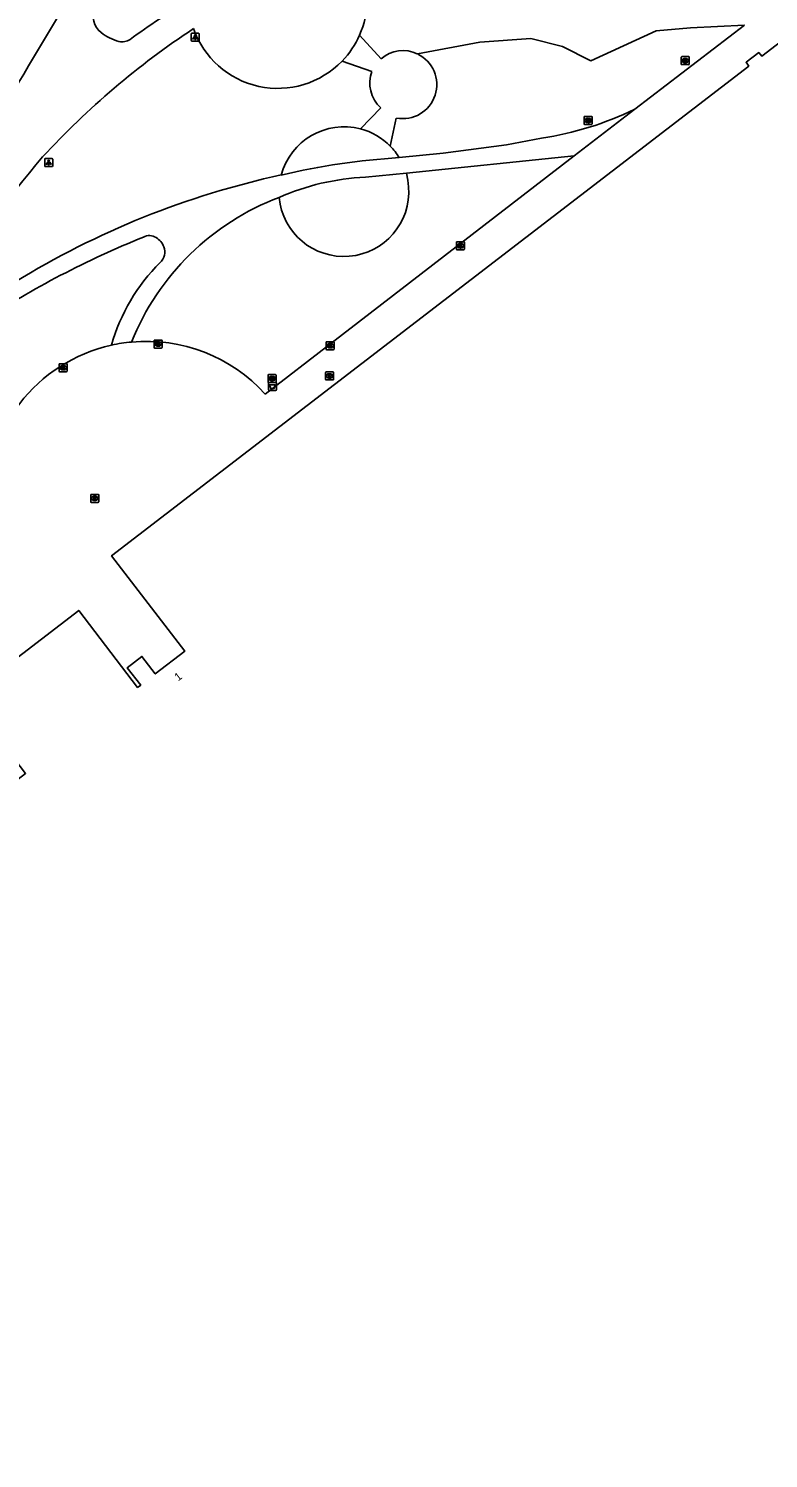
# Model space of a CAD drawing. Extents: x 155209 to 156823, y 385356 to 388482.
# Drawn here: x 156040.2 to 156132.6, y 385768.7 to 385947.3 of the extents above; entities that cross this region are included whole.
import ezdxf

# ---------------------------------------------------------------- set-up
doc = ezdxf.new("R2010")
doc.units = 0
for name, color, linetype in [('IMGEO_Afvalbak', 7, 'Continuous'), ('IMGEO_Brandkraan', 7, 'Continuous'), ('IMGEO_Groenvoorziening', 7, 'Continuous'), ('IMGEO_Kolk', 7, 'Continuous'), ('IMGEO_Lichtpunt', 7, 'Continuous'), ('IMGEO_Pand', 7, 'Continuous'), ('IMGEO_Pand_nummerreeks', 7, 'Continuous'), ('IMGEO_Rioolput', 7, 'Continuous'), ('IMGEO_Voetpad_gesloten', 7, 'Continuous'), ('IMGEO_Voetpad_open', 7, 'Continuous')]:
    doc.layers.add(name, color=color, linetype=linetype)

msp = doc.modelspace()

# ---------------------------------------------------------------- linework, layer by layer
at = {"layer": 'IMGEO_Afvalbak'}
for p, q in [((156070.18, 385902.2), (156070.18, 385903)), ((156070.18, 385903), (156070.18, 385902.2)), ((156070.28, 385903.1), (156071.07, 385903.1)), ((156071.07, 385903.1), (156070.28, 385903.1)), ((156071.07, 385902.1), (156070.28, 385902.1)), ((156070.28, 385902.1), (156071.07, 385902.1)), ((156071.17, 385903), (156071.17, 385902.2)), ((156071.17, 385902.2), (156071.17, 385903))]:
    msp.add_line(p, q, dxfattribs=at)
msp.add_lwpolyline([(156070.32, 385902.81), (156071.02, 385902.81), (156070.88, 385902.34), (156070.47, 385902.34), (156070.32, 385902.81)], dxfattribs=at)
for centre, start, end in [((156070.28, 385903), 90, 180), ((156070.28, 385903), 90, 180), ((156070.28, 385902.2), 180, 270), ((156070.28, 385902.2), 180, 270), ((156071.07, 385903), 0, 90), ((156071.07, 385903), 360, 90), ((156071.07, 385902.2), 270, 0), ((156071.07, 385902.2), 270, 0)]:
    msp.add_arc(centre, 0.1, start, end, dxfattribs=at)
at = {"layer": 'IMGEO_Brandkraan'}
for p, q in [((156077.31, 385903.49), (156077.31, 385904.34)), ((156077.39, 385904.42), (156078.24, 385904.42)), ((156078.24, 385903.41), (156077.39, 385903.41)), ((156077.8, 385904.19), (156077.83, 385904.19)), ((156077.82, 385903.64), (156077.8, 385903.64)), ((156078.31, 385904.34), (156078.31, 385903.49))]:
    msp.add_line(p, q, dxfattribs=at)
for points in [[(156077.31, 385903.49), (156077.31, 385904.34)], [(156077.39, 385904.42), (156078.24, 385904.42)], [(156078.24, 385903.41), (156077.39, 385903.41)], [(156077.66, 385904.11), (156077.66, 385903.71), (156077.87, 385903.71)], [(156077.89, 385904.11), (156077.66, 385904.11)], [(156077.84, 385904.03), (156077.79, 385904.03), (156077.79, 385903.96)], [(156077.79, 385903.96), (156077.84, 385903.96)], [(156077.85, 385903.88), (156077.79, 385903.88), (156077.79, 385903.8)], [(156077.79, 385903.8), (156077.85, 385903.8)], [(156078.31, 385904.34), (156078.31, 385903.49)]]:
    msp.add_lwpolyline(points, dxfattribs=at)
for centre, radius, start, end in [((156077.39, 385904.34), 0.0765, 91.552, 178.448), ((156077.39, 385904.34), 0.0765, 91.552, 178.448), ((156077.39, 385903.49), 0.0765, 181.552, 268.448), ((156077.39, 385903.49), 0.0765, 181.552, 268.448), ((156077.84, 385904), 0.0379, 267.8285, 90.9355), ((156077.85, 385903.84), 0.0404, 269.8759, 90.5077), ((156077.88, 385903.97), 0.251, 268.6676, 293.5347), ((156077.9, 385903.97), 0.145, 59.4692, 91.5367), ((156077.92, 385904.02), 0.0922, 285.5137, 58.1501), ((156077.93, 385903.83), 0.105, 301.3115, 78.989), ((156078.24, 385904.34), 0.0765, 1.552, 88.448), ((156078.24, 385904.34), 0.0765, 1.552, 88.448), ((156078.24, 385903.49), 0.0765, 271.552, 358.448), ((156078.24, 385903.49), 0.0765, 271.552, 358.448)]:
    msp.add_arc(centre, radius, start, end, dxfattribs=at)
for centre, major_axis, ratio, start_param, end_param in [((156077.8, 385903.91), (-0.387, 0.002), 0.722429, 4.712389, 7.853982), ((156077.82, 385903.91), (-0.39, 0.002), 0.717154, 1.570796, 4.712389)]:
    msp.add_ellipse(centre, major_axis=major_axis, ratio=ratio, start_param=start_param, end_param=end_param, dxfattribs=at)
at = {"layer": 'IMGEO_Groenvoorziening'}
for points in [[(156084.25, 385943.54), (156081.55, 385946.49)], [(156129.61, 385947.73), (156122.86, 385947.41), (156118.61, 385947.02), (156110.43, 385943.26), (156106.89, 385945.06), (156102.94, 385946.08), (156096.56, 385945.6), (156088.77, 385944.15)], [(156079.38, 385943.25), (156083.08, 385941.96)], [(156084.2, 385937.41), (156081.68, 385934.78)], [(156085.39, 385932.62), (156086.14, 385936.13)], [(156087.42, 385929.26), (156087.57, 385928.37), (156087.68, 385927.52)]]:
    msp.add_lwpolyline(points, dxfattribs=at)
for centre, radius, start, end in [((156086.96, 385940.46), 4.1, 63.8546, 131.4393), ((156086.95, 385940.3), 4.25, 259.1315, 64.6041), ((156087.1, 385940.53), 4.27, 160.4691, 227.0936), ((156079.61, 385926.94), 8.1, 75.2179, 165.1912), ((156079.61, 385926.94), 8.1, 44.5182, 75.24), ((156079.6, 385926.93), 8.11, 31.5996, 44.4923), ((156079.59, 385926.94), 8.11, 185.2268, 4.1109)]:
    msp.add_arc(centre, radius, start, end, dxfattribs=at)
at = {"layer": 'IMGEO_Kolk'}
for p, q in [((156093.65, 385919.74), (156093.65, 385920.6)), ((156093.72, 385920.67), (156094.58, 385920.67)), ((156094.58, 385919.67), (156093.72, 385919.67)), ((156094.16, 385919.89), (156094.13, 385919.89)), ((156094.14, 385920.45), (156094.16, 385920.45)), ((156094.65, 385920.6), (156094.65, 385919.74)), ((156055.89, 385907.46), (156055.89, 385908.32)), ((156055.97, 385908.39), (156056.82, 385908.39)), ((156056.82, 385907.39), (156055.97, 385907.39)), ((156056.38, 385908.17), (156056.41, 385908.17)), ((156056.4, 385907.61), (156056.38, 385907.61)), ((156056.89, 385908.32), (156056.89, 385907.46)), ((156077.38, 385907.25), (156077.38, 385908.11)), ((156077.45, 385908.18), (156078.3, 385908.18)), ((156078.3, 385907.18), (156077.45, 385907.18)), ((156077.86, 385907.96), (156077.89, 385907.96)), ((156077.89, 385907.4), (156077.86, 385907.4)), ((156078.38, 385908.11), (156078.38, 385907.25)), ((156044.03, 385904.5), (156044.03, 385905.36)), ((156044.11, 385905.43), (156044.96, 385905.43)), ((156044.52, 385905.21), (156044.55, 385905.21)), ((156045.03, 385905.36), (156045.03, 385904.5)), ((156044.96, 385904.43), (156044.11, 385904.43)), ((156044.54, 385904.65), (156044.52, 385904.65))]:
    msp.add_line(p, q, dxfattribs=at)
for points in [[(156093.65, 385919.74), (156093.65, 385920.6)], [(156093.72, 385920.67), (156094.58, 385920.67)], [(156094.58, 385919.67), (156093.72, 385919.67)], [(156093.97, 385920.37), (156094.09, 385920.37), (156094.09, 385920.22), (156094.22, 385920.37), (156094.39, 385920.37), (156094.24, 385920.22), (156094.39, 385919.97), (156094.24, 385919.97), (156094.16, 385920.14), (156094.09, 385920.07), (156094.09, 385919.97), (156093.97, 385919.97), (156093.97, 385920.37)], [(156094.65, 385920.6), (156094.65, 385919.74)], [(156055.89, 385907.46), (156055.89, 385908.32)], [(156055.97, 385908.39), (156056.82, 385908.39)], [(156056.82, 385907.39), (156055.97, 385907.39)], [(156056.21, 385908.09), (156056.34, 385908.09), (156056.34, 385907.94), (156056.47, 385908.09), (156056.63, 385908.09), (156056.49, 385907.94), (156056.64, 385907.69), (156056.49, 385907.69), (156056.4, 385907.85), (156056.34, 385907.79), (156056.34, 385907.69), (156056.21, 385907.69), (156056.21, 385908.09)], [(156056.89, 385908.32), (156056.89, 385907.46)], [(156077.38, 385907.25), (156077.38, 385908.11)], [(156077.45, 385908.18), (156078.3, 385908.18)], [(156078.3, 385907.18), (156077.45, 385907.18)], [(156077.7, 385907.88), (156077.82, 385907.88), (156077.82, 385907.73), (156077.95, 385907.88), (156078.11, 385907.88), (156077.97, 385907.73), (156078.12, 385907.48), (156077.97, 385907.48), (156077.88, 385907.65), (156077.82, 385907.58), (156077.82, 385907.48), (156077.7, 385907.48), (156077.7, 385907.88)], [(156078.38, 385908.11), (156078.38, 385907.25)], [(156044.03, 385904.5), (156044.03, 385905.36)], [(156044.11, 385905.43), (156044.96, 385905.43)], [(156044.35, 385905.13), (156044.48, 385905.13), (156044.48, 385904.98), (156044.61, 385905.13), (156044.77, 385905.13), (156044.63, 385904.98), (156044.78, 385904.73), (156044.63, 385904.73), (156044.54, 385904.89), (156044.48, 385904.83), (156044.48, 385904.73), (156044.35, 385904.73), (156044.35, 385905.13)], [(156045.03, 385905.36), (156045.03, 385904.5)], [(156044.96, 385904.43), (156044.11, 385904.43)]]:
    msp.add_lwpolyline(points, dxfattribs=at)
for centre, start, end in [((156093.73, 385920.6), 91.552, 178.448), ((156093.73, 385920.6), 91.552, 178.448), ((156093.73, 385919.75), 181.552, 268.448), ((156093.73, 385919.75), 181.552, 268.448), ((156094.57, 385920.6), 1.552, 88.448), ((156094.57, 385920.6), 1.552, 88.448), ((156094.57, 385919.75), 271.552, 358.448), ((156094.57, 385919.75), 271.552, 358.448), ((156055.97, 385908.31), 91.552, 178.448), ((156055.97, 385908.31), 91.552, 178.448), ((156055.97, 385907.46), 181.552, 268.448), ((156055.97, 385907.46), 181.552, 268.448), ((156056.82, 385908.31), 1.552, 88.448), ((156056.82, 385908.31), 1.552, 88.448), ((156056.82, 385907.46), 271.552, 358.448), ((156056.82, 385907.46), 271.552, 358.448), ((156077.45, 385908.11), 91.552, 178.448), ((156077.45, 385908.11), 91.552, 178.448), ((156077.45, 385907.26), 181.552, 268.448), ((156077.45, 385907.26), 181.552, 268.448), ((156078.3, 385908.11), 1.552, 88.448), ((156078.3, 385908.11), 1.552, 88.448), ((156078.3, 385907.26), 271.552, 358.448), ((156078.3, 385907.26), 271.552, 358.448), ((156044.11, 385905.35), 91.552, 178.448), ((156044.11, 385905.35), 91.552, 178.448), ((156044.96, 385905.35), 1.552, 88.448), ((156044.96, 385905.35), 1.552, 88.448), ((156044.11, 385904.51), 181.552, 268.448), ((156044.11, 385904.51), 181.552, 268.448), ((156044.96, 385904.51), 271.552, 358.448), ((156044.96, 385904.51), 271.552, 358.448)]:
    msp.add_arc(centre, 0.0765, start, end, dxfattribs=at)
for centre, major_axis, ratio, start_param, end_param in [((156094.14, 385920.17), (-0.387, 0.002), 0.722429, 4.712389, 7.853982), ((156094.16, 385920.17), (-0.39, 0.002), 0.717154, 1.570796, 4.712389), ((156056.38, 385907.89), (-0.387, 0.002), 0.722429, 4.712389, 7.853982), ((156056.4, 385907.89), (-0.39, 0.002), 0.717154, 1.570796, 4.712389), ((156077.86, 385907.68), (-0.387, 0.002), 0.722429, 4.712389, 7.853982), ((156077.89, 385907.68), (-0.39, 0.002), 0.717154, 1.570796, 4.712389), ((156044.52, 385904.93), (-0.387, 0.002), 0.722429, 4.712389, 7.853982), ((156044.54, 385904.93), (-0.39, 0.002), 0.717154, 1.570796, 4.712389)]:
    msp.add_ellipse(centre, major_axis=major_axis, ratio=ratio, start_param=start_param, end_param=end_param, dxfattribs=at)
at = {"layer": 'IMGEO_Lichtpunt'}
for p, q in [((156060.53, 385946.62), (156060.53, 385945.82)), ((156060.53, 385946.62), (156060.53, 385945.82)), ((156061.43, 385946.72), (156060.63, 385946.72)), ((156061.43, 385946.72), (156060.63, 385946.72)), ((156061.53, 385945.82), (156061.53, 385946.62)), ((156061.53, 385945.82), (156061.53, 385946.62)), ((156060.63, 385945.72), (156061.43, 385945.72)), ((156060.63, 385945.72), (156061.43, 385945.72)), ((156042.24, 385930.97), (156042.24, 385930.16)), ((156042.24, 385930.97), (156042.24, 385930.16)), ((156043.14, 385931.06), (156042.33, 385931.06)), ((156043.14, 385931.06), (156042.33, 385931.06)), ((156043.23, 385930.16), (156043.23, 385930.97)), ((156043.23, 385930.16), (156043.23, 385930.97)), ((156042.33, 385930.06), (156043.14, 385930.06)), ((156042.33, 385930.06), (156043.14, 385930.06))]:
    msp.add_line(p, q, dxfattribs=at)
for points in [[(156060.91, 385946.29), (156060.94, 385946.26), (156060.76, 385946), (156060.72, 385946.02), (156060.91, 385946.29)], [(156061.01, 385946.24), (156061.05, 385946.24), (156061.05, 385945.92), (156061.01, 385945.92), (156061.01, 385946.24)], [(156061.12, 385946.26), (156061.16, 385946.29), (156061.34, 385946.02), (156061.3, 385946), (156061.12, 385946.26)], [(156042.61, 385930.63), (156042.65, 385930.6), (156042.46, 385930.34), (156042.42, 385930.37), (156042.61, 385930.63)], [(156042.71, 385930.58), (156042.76, 385930.58), (156042.76, 385930.26), (156042.71, 385930.26), (156042.71, 385930.58)], [(156042.82, 385930.6), (156042.86, 385930.63), (156043.05, 385930.37), (156043.01, 385930.34), (156042.82, 385930.6)]]:
    msp.add_lwpolyline(points, dxfattribs=at)
for centre in [(156061.03, 385946.42), (156042.74, 385930.76)]:
    msp.add_circle(centre, 0.0994, dxfattribs=at)
for centre, start, end in [((156060.63, 385946.62), 90, 180), ((156060.63, 385946.62), 90, 180), ((156061.43, 385946.62), 0, 90), ((156061.43, 385946.62), 0, 90), ((156060.63, 385945.82), 180, 270), ((156060.63, 385945.82), 180, 270), ((156061.43, 385945.82), 270, 0), ((156061.43, 385945.82), 270, 360), ((156042.33, 385930.97), 90, 180), ((156042.33, 385930.97), 90, 180), ((156042.33, 385930.16), 180, 270), ((156042.33, 385930.16), 180, 270), ((156043.14, 385930.97), 0, 90), ((156043.14, 385930.97), 0, 90), ((156043.14, 385930.16), 270, 0), ((156043.14, 385930.16), 270, 360)]:
    msp.add_arc(centre, 0.0946, start, end, dxfattribs=at)
at = {"layer": 'IMGEO_Pand'}
msp.add_lwpolyline([(155903.94, 385768.67), (155939.8, 385796.26), (156025.75, 385862.36), (156024.52, 385863.94), (156026.12, 385865.17), (156036.49, 385851.68), (156039.84, 385854.25), (156032.47, 385863.87), (156046.48, 385874.61), (156053.84, 385865), (156054.22, 385865.29), (156052.55, 385867.46), (156054.37, 385868.86), (156056.04, 385866.68), (156059.72, 385869.51), (156050.59, 385881.44), (156130.16, 385942.62), (156129.82, 385943.1), (156131.41, 385944.3), (156131.77, 385943.86), (156170.13, 385973.36)], dxfattribs=at)
at = {"layer": 'IMGEO_Rioolput'}
for p, q in [((156121.72, 385942.87), (156121.72, 385943.73)), ((156121.79, 385943.8), (156122.64, 385943.8)), ((156122.64, 385942.8), (156121.79, 385942.8)), ((156122.2, 385943.58), (156122.23, 385943.58)), ((156122.23, 385943.02), (156122.2, 385943.02)), ((156122.72, 385943.73), (156122.72, 385942.87)), ((156109.59, 385935.4), (156109.59, 385936.25)), ((156109.67, 385936.32), (156110.52, 385936.32)), ((156110.08, 385936.1), (156110.11, 385936.1)), ((156110.1, 385935.54), (156110.08, 385935.54)), ((156110.59, 385936.25), (156110.59, 385935.4)), ((156110.52, 385935.32), (156109.67, 385935.32)), ((156070.13, 385903.15), (156070.13, 385904.01)), ((156070.21, 385904.08), (156071.06, 385904.08)), ((156070.62, 385903.86), (156070.65, 385903.86)), ((156071.13, 385904.01), (156071.13, 385903.15)), ((156071.06, 385903.08), (156070.21, 385903.08)), ((156070.64, 385903.3), (156070.62, 385903.3)), ((156047.98, 385888.18), (156047.98, 385889.03)), ((156048.06, 385889.11), (156048.91, 385889.11)), ((156048.98, 385889.03), (156048.98, 385888.18)), ((156048.91, 385888.11), (156048.06, 385888.11)), ((156048.47, 385888.89), (156048.5, 385888.89)), ((156048.49, 385888.33), (156048.47, 385888.33))]:
    msp.add_line(p, q, dxfattribs=at)
for points in [[(156121.72, 385942.87), (156121.72, 385943.73)], [(156121.79, 385943.8), (156122.64, 385943.8)], [(156122.64, 385942.8), (156121.79, 385942.8)], [(156122.31, 385943.5), (156122.05, 385943.5), (156122.05, 385943.1)], [(156122.05, 385943.1), (156122.18, 385943.1), (156122.18, 385943.26), (156122.19, 385943.26)], [(156122.23, 385943.42), (156122.18, 385943.42), (156122.18, 385943.34)], [(156122.18, 385943.34), (156122.23, 385943.34)], [(156122.23, 385943.23), (156122.31, 385943.1), (156122.45, 385943.1), (156122.38, 385943.23)], [(156122.72, 385943.73), (156122.72, 385942.87)], [(156109.59, 385935.4), (156109.59, 385936.25)], [(156109.67, 385936.32), (156110.52, 385936.32)], [(156110.18, 385936.02), (156109.93, 385936.02), (156109.93, 385935.62)], [(156109.93, 385935.62), (156110.05, 385935.62), (156110.05, 385935.79), (156110.06, 385935.79)], [(156110.11, 385935.94), (156110.05, 385935.94), (156110.05, 385935.86)], [(156110.05, 385935.86), (156110.1, 385935.86)], [(156110.11, 385935.76), (156110.18, 385935.62), (156110.32, 385935.62), (156110.26, 385935.75)], [(156110.59, 385936.25), (156110.59, 385935.4)], [(156110.52, 385935.32), (156109.67, 385935.32)], [(156070.13, 385903.15), (156070.13, 385904.01)], [(156070.21, 385904.08), (156071.06, 385904.08)], [(156070.72, 385903.78), (156070.47, 385903.78), (156070.47, 385903.38)], [(156070.47, 385903.38), (156070.59, 385903.38), (156070.59, 385903.54), (156070.6, 385903.54)], [(156070.65, 385903.7), (156070.59, 385903.7), (156070.59, 385903.62)], [(156070.59, 385903.62), (156070.64, 385903.62)], [(156070.65, 385903.51), (156070.72, 385903.38), (156070.86, 385903.38), (156070.8, 385903.51)], [(156071.13, 385904.01), (156071.13, 385903.15)], [(156071.06, 385903.08), (156070.21, 385903.08)], [(156047.98, 385888.18), (156047.98, 385889.03)], [(156048.06, 385889.11), (156048.91, 385889.11)], [(156048.98, 385889.03), (156048.98, 385888.18)], [(156048.91, 385888.11), (156048.06, 385888.11)], [(156048.57, 385888.81), (156048.32, 385888.81), (156048.32, 385888.41)], [(156048.32, 385888.41), (156048.44, 385888.41), (156048.44, 385888.57), (156048.45, 385888.57)], [(156048.5, 385888.73), (156048.44, 385888.73), (156048.44, 385888.65)], [(156048.44, 385888.65), (156048.49, 385888.65)], [(156048.5, 385888.54), (156048.57, 385888.41), (156048.71, 385888.41), (156048.65, 385888.53)]]:
    msp.add_lwpolyline(points, dxfattribs=at)
for centre, radius, start, end in [((156121.79, 385943.72), 0.0765, 91.552, 178.448), ((156121.79, 385943.72), 0.0765, 91.552, 178.448), ((156121.79, 385942.87), 0.0765, 181.552, 268.448), ((156121.79, 385942.87), 0.0765, 181.552, 268.448), ((156122.19, 385943.21), 0.0533, 26.0293, 88.6989), ((156122.24, 385943.32), 0.0964, 77.0061, 93.1865), ((156122.21, 385943.53), 0.19, 274.7715, 282.9687), ((156122.25, 385943.38), 0.0378, 276.6634, 79.6772), ((156122.3, 385943.39), 0.109, 350.3612, 89.416), ((156122.3, 385943.39), 0.112, 277.5842, 350.9817), ((156122.29, 385943.17), 0.108, 29.5134, 73.7905), ((156122.64, 385943.72), 0.0765, 1.552, 88.448), ((156122.64, 385943.72), 0.0765, 1.552, 88.448), ((156122.64, 385942.87), 0.0765, 271.552, 358.448), ((156122.64, 385942.87), 0.0765, 271.552, 358.448), ((156109.67, 385936.25), 0.0765, 91.552, 178.448), ((156109.67, 385936.25), 0.0765, 91.552, 178.448), ((156110.06, 385935.73), 0.0533, 26.0293, 88.6989), ((156110.09, 385936.05), 0.19, 274.7715, 282.9687), ((156110.11, 385935.85), 0.0964, 77.0061, 93.1865), ((156110.13, 385935.9), 0.0378, 276.6634, 79.6772), ((156110.18, 385935.91), 0.109, 350.3612, 89.416), ((156110.18, 385935.91), 0.112, 277.5842, 350.9817), ((156110.16, 385935.7), 0.108, 29.5134, 73.7905), ((156110.52, 385936.25), 0.0765, 1.552, 88.448), ((156110.52, 385936.25), 0.0765, 1.552, 88.448), ((156109.67, 385935.4), 0.0765, 181.552, 268.448), ((156109.67, 385935.4), 0.0765, 181.552, 268.448), ((156110.52, 385935.4), 0.0765, 271.552, 358.448), ((156110.52, 385935.4), 0.0765, 271.552, 358.448), ((156070.21, 385904), 0.0765, 91.552, 178.448), ((156070.21, 385904), 0.0765, 91.552, 178.448), ((156070.6, 385903.49), 0.0533, 26.0293, 88.6989), ((156070.63, 385903.81), 0.19, 274.7715, 282.9687), ((156070.65, 385903.6), 0.0964, 77.0061, 93.1865), ((156070.67, 385903.66), 0.0378, 276.6634, 79.6772), ((156070.72, 385903.67), 0.109, 350.3612, 89.416), ((156070.72, 385903.67), 0.112, 277.5842, 350.9817), ((156070.7, 385903.45), 0.108, 29.5134, 73.7905), ((156071.06, 385904), 0.0765, 1.552, 88.448), ((156071.06, 385904), 0.0765, 1.552, 88.448), ((156070.21, 385903.16), 0.0765, 181.552, 268.448), ((156070.21, 385903.16), 0.0765, 181.552, 268.448), ((156071.06, 385903.16), 0.0765, 271.552, 358.448), ((156071.06, 385903.16), 0.0765, 271.552, 358.448), ((156048.06, 385889.03), 0.0765, 91.552, 178.448), ((156048.06, 385889.03), 0.0765, 91.552, 178.448), ((156048.91, 385889.03), 0.0765, 1.552, 88.448), ((156048.91, 385889.03), 0.0765, 1.552, 88.448), ((156048.06, 385888.18), 0.0765, 181.552, 268.448), ((156048.06, 385888.18), 0.0765, 181.552, 268.448), ((156048.45, 385888.52), 0.0533, 26.0293, 88.6989), ((156048.48, 385888.84), 0.19, 274.7715, 282.9687), ((156048.5, 385888.63), 0.0964, 77.0061, 93.1865), ((156048.52, 385888.69), 0.0378, 276.6634, 79.6772), ((156048.57, 385888.7), 0.109, 350.3612, 89.416), ((156048.57, 385888.7), 0.112, 277.5842, 350.9817), ((156048.55, 385888.48), 0.108, 29.5134, 73.7905), ((156048.91, 385888.18), 0.0765, 271.552, 358.448), ((156048.91, 385888.18), 0.0765, 271.552, 358.448)]:
    msp.add_arc(centre, radius, start, end, dxfattribs=at)
for centre, major_axis, ratio, start_param, end_param in [((156122.2, 385943.3), (-0.387, 0.002), 0.722429, 4.712389, 7.853982), ((156122.23, 385943.3), (-0.39, 0.002), 0.717154, 1.570796, 4.712389), ((156110.08, 385935.82), (-0.387, 0.002), 0.722429, 4.712389, 7.853982), ((156110.1, 385935.82), (-0.39, 0.002), 0.717154, 1.570796, 4.712389), ((156070.62, 385903.58), (-0.387, 0.002), 0.722429, 4.712389, 7.853982), ((156070.64, 385903.58), (-0.39, 0.002), 0.717154, 1.570796, 4.712389), ((156048.47, 385888.61), (-0.387, 0.002), 0.722429, 4.712389, 7.853982), ((156048.49, 385888.61), (-0.39, 0.002), 0.717154, 1.570796, 4.712389)]:
    msp.add_ellipse(centre, major_axis=major_axis, ratio=ratio, start_param=start_param, end_param=end_param, dxfattribs=at)
at = {"layer": 'IMGEO_Voetpad_gesloten'}
for points in [[(156040.22, 385942.63), (156048.97, 385957.27), (156063.23, 385980.59)], [(156115.91, 385937.22), (156108.35, 385931.39)], [(156086.51, 385931.19), (156091.98, 385931.72), (156099.92, 385932.8), (156104.29, 385933.61)], [(156108.35, 385931.39), (156087.42, 385929.26)], [(156082.29, 385928.73), (156087.42, 385929.26)]]:
    msp.add_lwpolyline(points, dxfattribs=at)
for centre, radius, start, end in [((156050.72, 385948.77), 2.43, 153.1075, 233.5509), ((156099.02, 385883.85), 77.35, 120.0542, 126.607), ((156117.03, 385862.17), 102.02, 123.4357, 137.3635), ((156052.98, 385951.47), 5.95, 231.52, 255.679), ((156051.94, 385947.37), 1.72, 255.5265, 303.9058), ((156291.79, 385789.4), 294.56, 148.6534, 152.3219), ((156098.29, 385973.53), 40.36, 278.5544, 295.8873), ((156111.53, 385871.22), 91.89, 139.1957, 152.0526), ((156092.27, 385841.18), 90.19, 93.661, 103.1334), ((156094.21, 385825.28), 106.13, 102.2026, 121.6536), ((156083.55, 385899.12), 29.64, 92.446, 113.9693), ((156082.86, 385896.19), 32.09, 110.7146, 158.149), ((156097.48, 385814.6), 114.96, 111.9238, 123.2752), ((156055.31, 385919.92), 1.53, 56.8249, 119.3448), ((156055.05, 385919.28), 2.2, 20.4005, 60.2965), ((156055.47, 385919.39), 1.77, 311.4548, 21.768), ((156072.98, 385901.54), 23.24, 134.6647, 164.4809), ((156054.74, 385888.64), 19.57, 94.8735, 102.2667)]:
    msp.add_arc(centre, radius, start, end, dxfattribs=at)
at = {"layer": 'IMGEO_Voetpad_open'}
for points in [[(156129.61, 385947.73), (156115.91, 385937.22)], [(156108.35, 385931.39), (156077.97, 385907.97), (156069.76, 385901.65)]]:
    msp.add_lwpolyline(points, dxfattribs=at)
for centre, radius, start, end in [((156071.35, 385950.98), 11.15, 336.253, 21.7943), ((156071.34, 385950.98), 11.15, 199.2367, 316.1295), ((156071.35, 385950.97), 11.14, 316.1179, 336.2738), ((156054.94, 385888.24), 20, 102.5867, 182.0635), ((156054.96, 385888.26), 19.96, 42.1353, 95.3998)]:
    msp.add_arc(centre, radius, start, end, dxfattribs=at)

# ---------------------------------------------------------------- texts
at = {"layer": 'IMGEO_Pand_nummerreeks'}
msp.add_text('1', height=1, rotation=37.5058, dxfattribs=at).set_placement((156058.9, 385865.73))

doc.saveas('drawing.dxf')
